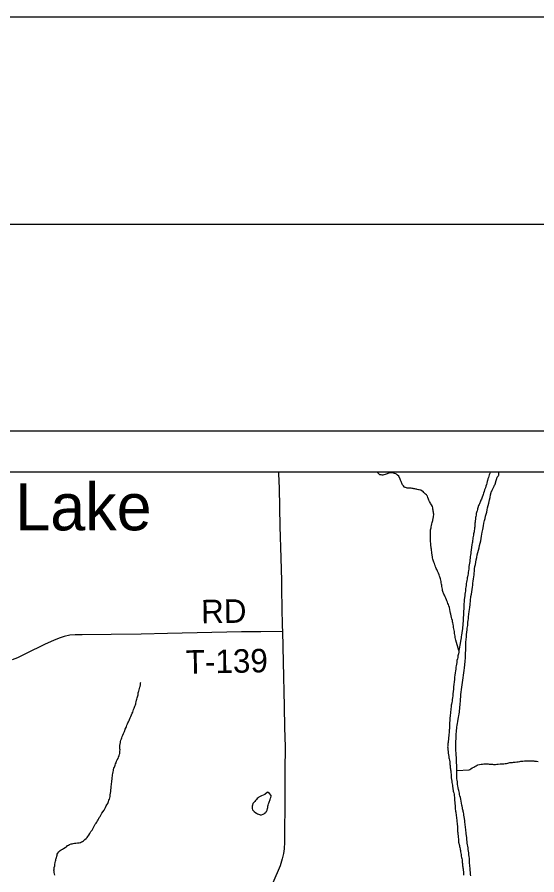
# Model space of a CAD drawing. Extents: x 10.6 to 44.6, y -2.6 to 23.4.
# Drawn here: x 16.174 to 17.431, y 21.353 to 23.426 of the extents above; entities that cross this region are included whole.
import ezdxf

# ---------------------------------------------------------------- set-up
doc = ezdxf.new("R2010")
doc.units = 0
for name, color, linetype in [('GM_X_County', 7, 'Continuous'), ('GM_X_County_Road', 7, 'Continuous'), ('GM_X_Major_River', 7, 'Continuous'), ('GM_X_Minor_Lake', 7, 'Continuous'), ('GM_X_Minor_Lake_Text', 7, 'Continuous'), ('GM_X_Minor_River', 7, 'Continuous'), ('GM_X_Township', 7, 'Continuous'), ('GM_X_Township_Road', 7, 'Continuous'), ('GM_X_Township_Road_Text', 7, 'Continuous'), ('SH_Border', 7, 'Continuous'), ('SH_Cut_Line', 7, 'Continuous'), ('SH_Data', 7, 'Continuous')]:
    doc.layers.add(name, color=color, linetype=linetype)

msp = doc.modelspace()

# ---------------------------------------------------------------- linework, layer by layer
at = {"layer": 'GM_X_County'}
msp.add_lwpolyline([(20.0033, 15.5302), (20.0033, 22.3267), (13.2033, 22.3267), (13.2033, 15.5267), (19.8413, 15.5267)], dxfattribs=at)
at = {"layer": 'GM_X_County_Road'}
msp.add_lwpolyline([(16.8061, 22.3267), (16.8061, 22.3229), (16.8073, 22.2883), (16.8094, 22.1953), (16.8119, 22.1196), (16.8129, 22.0638), (16.8133, 22.0423), (16.8148, 21.9554), (16.8155, 21.9415), (16.817, 21.868), (16.8194, 21.7601), (16.8208, 21.7092), (16.8218, 21.6629), (16.8216, 21.6055), (16.8211, 21.5206), (16.8206, 21.4588), (16.8206, 21.4326), (16.8194, 21.4166), (16.8177, 21.4047), (16.8148, 21.3924), (16.8097, 21.3754), (16.7927, 21.3342)], dxfattribs=at)
at = {"layer": 'GM_X_Major_River'}
for points in [[(17.3176, 22.3267), (17.3169, 22.3237), (17.3158, 22.3203), (17.3147, 22.3169), (17.3137, 22.3134), (17.3126, 22.3104), (17.3115, 22.3069), (17.3108, 22.3039), (17.3098, 22.3004), (17.3087, 22.2966), (17.3073, 22.2928), (17.3062, 22.2886), (17.3044, 22.2836), (17.3034, 22.2798), (17.3019, 22.2759), (17.3009, 22.2725), (17.2976, 22.2641), (17.2969, 22.2614), (17.2954, 22.2591), (17.2947, 22.2568), (17.2936, 22.2545), (17.2925, 22.2525), (17.2918, 22.2503), (17.2911, 22.2483), (17.29, 22.246), (17.2882, 22.2403), (17.2875, 22.238), (17.2872, 22.2361), (17.2861, 22.2334), (17.2858, 22.2315)], [(17.3207, 22.2805), (17.3219, 22.2804), (17.3219, 22.281), (17.3226, 22.2829), (17.3245, 22.2861), (17.3258, 22.29), (17.3277, 22.2925), (17.3283, 22.2951), (17.3296, 22.297), (17.3303, 22.2983), (17.3309, 22.2989), (17.3309, 22.2996), (17.3309, 22.3008), (17.3347, 22.3143), (17.3373, 22.3168), (17.3379, 22.3187), (17.3386, 22.3194), (17.3386, 22.3213), (17.3392, 22.3251), (17.3396, 22.3267)], [(17.2762, 22.0584), (17.2768, 22.0634), (17.2778, 22.0691), (17.2785, 22.074), (17.2788, 22.0786), (17.2791, 22.0828), (17.2797, 22.0874), (17.28, 22.0927), (17.281, 22.0984), (17.282, 22.1038), (17.2831, 22.1091), (17.2841, 22.1148), (17.2855, 22.1205), (17.2865, 22.127), (17.2883, 22.1328), (17.2897, 22.1381), (17.2911, 22.1435), (17.2921, 22.1496), (17.2935, 22.1553), (17.2949, 22.161), (17.2959, 22.1667), (17.2969, 22.1721), (17.298, 22.1771), (17.2986, 22.182), (17.3, 22.1881), (17.3017, 22.1969), (17.3027, 22.2034), (17.3045, 22.2095), (17.3059, 22.2148), (17.3069, 22.2202), (17.308, 22.2255), (17.3094, 22.2301), (17.3104, 22.2355), (17.3118, 22.2404), (17.3132, 22.2462), (17.3146, 22.2519), (17.316, 22.2595), (17.3177, 22.2656), (17.3188, 22.2717), (17.3202, 22.2775), (17.3207, 22.2805)], [(17.2858, 22.2315), (17.285, 22.2292), (17.2843, 22.2265), (17.284, 22.2246), (17.2837, 22.2227), (17.283, 22.2197), (17.2826, 22.2174), (17.2823, 22.2147), (17.282, 22.2117), (17.2817, 22.2098), (17.2813, 22.2078), (17.2814, 22.2059), (17.281, 22.2037), (17.2811, 22.2018), (17.2807, 22.1999), (17.2808, 22.1976), (17.2805, 22.1949), (17.2801, 22.1922), (17.2798, 22.1892), (17.2795, 22.1858), (17.2788, 22.1823), (17.2778, 22.1778), (17.2775, 22.1747), (17.2768, 22.1713), (17.2761, 22.1678), (17.2758, 22.1648), (17.2755, 22.1617), (17.2751, 22.1598), (17.2748, 22.1576), (17.2741, 22.1553), (17.2738, 22.1515), (17.2718, 22.1381), (17.2711, 22.1339), (17.2708, 22.1297), (17.2701, 22.1259), (17.2698, 22.1225), (17.2695, 22.1187), (17.2689, 22.1149), (17.2686, 22.1107), (17.2679, 22.1065), (17.2672, 22.1027), (17.2665, 22.0985), (17.2659, 22.0928), (17.2652, 22.0886), (17.2646, 22.0848), (17.2643, 22.081), (17.2636, 22.0775), (17.2633, 22.0741), (17.2626, 22.0714), (17.2622, 22.0684), (17.2616, 22.0649), (17.2609, 22.0611), (17.2602, 22.0573), (17.2595, 22.0531), (17.2589, 22.0485), (17.2585, 22.0455), (17.2582, 22.0424), (17.2579, 22.0394), (17.2572, 22.0356), (17.2569, 22.0318), (17.2567, 22.0276), (17.256, 22.0234), (17.2553, 22.0184), (17.2551, 22.0135), (17.2544, 22.0085), (17.2541, 22.0028), (17.2538, 21.999), (17.2539, 21.9956), (17.2536, 21.9918), (17.2533, 21.988), (17.2534, 21.9842), (17.2531, 21.98), (17.2528, 21.9762), (17.2529, 21.9728), (17.2526, 21.969), (17.2523, 21.9656), (17.252, 21.9614), (17.2517, 21.9561), (17.251, 21.9519), (17.2507, 21.9481), (17.2501, 21.9439), (17.2488, 21.9328), (17.2481, 21.9294), (17.2478, 21.926), (17.2471, 21.9221), (17.2464, 21.918), (17.2454, 21.9126), (17.2448, 21.9084), (17.2437, 21.9038), (17.243, 21.8996), (17.2424, 21.8954), (17.2417, 21.8916), (17.241, 21.8878), (17.2403, 21.8851), (17.2396, 21.8825), (17.2393, 21.879), (17.2386, 21.8756), (17.2375, 21.8718), (17.2369, 21.8665), (17.2362, 21.8623), (17.2359, 21.8585)], [(17.242, 21.5569), (17.2412, 21.5599), (17.2403, 21.5641), (17.2395, 21.5683), (17.239, 21.5717), (17.2386, 21.5751), (17.2385, 21.5785), (17.2381, 21.5819), (17.2376, 21.5857), (17.2375, 21.5891), (17.2374, 21.5933), (17.2373, 21.5975), (17.2369, 21.6016), (17.2372, 21.6058), (17.237, 21.6111), (17.237, 21.6153), (17.2369, 21.6195), (17.2368, 21.6237), (17.2367, 21.6275), (17.2366, 21.6313), (17.2362, 21.6347), (17.2361, 21.6381), (17.2356, 21.6419), (17.2356, 21.6453), (17.2355, 21.6487), (17.235, 21.6529), (17.2349, 21.6567), (17.2349, 21.6601), (17.2348, 21.6639), (17.2347, 21.6685), (17.235, 21.6734), (17.2352, 21.6776), (17.2355, 21.6814), (17.2355, 21.6848), (17.2358, 21.6879), (17.2357, 21.6913), (17.236, 21.6943), (17.2363, 21.6989), (17.2366, 21.7027), (17.2373, 21.7069), (17.2376, 21.7107), (17.2382, 21.7149), (17.2389, 21.7191), (17.2396, 21.7237), (17.2416, 21.7343), (17.2419, 21.7378), (17.2426, 21.7427), (17.2433, 21.7465), (17.2436, 21.7503), (17.2442, 21.7545), (17.2445, 21.7591), (17.2452, 21.7633), (17.2455, 21.7679), (17.2458, 21.7724), (17.246, 21.7777), (17.2467, 21.7835), (17.2469, 21.7892), (17.2476, 21.7949), (17.2486, 21.8017), (17.2496, 21.8071), (17.2502, 21.8124), (17.2513, 21.8181), (17.2519, 21.8242), (17.2525, 21.8299), (17.2532, 21.8357), (17.2538, 21.8414), (17.2548, 21.8475), (17.2554, 21.8539), (17.2564, 21.8608), (17.2574, 21.8699), (17.2583, 21.8776), (17.2586, 21.8844), (17.2585, 21.8901), (17.2587, 21.8958), (17.259, 21.9023), (17.2592, 21.9091), (17.2594, 21.9156), (17.2601, 21.922), (17.2607, 21.9285), (17.2609, 21.9342), (17.2616, 21.9396), (17.2622, 21.9453), (17.2625, 21.9495), (17.2628, 21.9529), (17.2635, 21.9563), (17.2638, 21.9601), (17.2641, 21.9643), (17.2648, 21.9685), (17.2651, 21.9727), (17.2653, 21.9773), (17.266, 21.9833), (17.2673, 21.9902), (17.2683, 21.9997), (17.2696, 22.007), (17.2715, 22.026), (17.2725, 22.0317), (17.2732, 22.0378), (17.2742, 22.0432), (17.2748, 22.0485), (17.2759, 22.0539), (17.2762, 22.0584)], [(17.2359, 21.8585), (17.2352, 21.855), (17.2346, 21.8508), (17.2339, 21.8463), (17.2333, 21.8413), (17.2326, 21.836), (17.232, 21.831), (17.2313, 21.8257), (17.2307, 21.82), (17.2301, 21.8131), (17.2294, 21.8078), (17.2288, 21.8024), (17.2281, 21.7967), (17.2275, 21.791), (17.2272, 21.7857), (17.2266, 21.7811), (17.2259, 21.7769), (17.2256, 21.7731), (17.2249, 21.7697), (17.2246, 21.7663), (17.2239, 21.7632), (17.2236, 21.759), (17.2229, 21.7556), (17.2226, 21.7518), (17.2223, 21.7484), (17.222, 21.7457), (17.2217, 21.743), (17.2214, 21.74), (17.221, 21.7369), (17.2207, 21.7331), (17.2204, 21.7297), (17.2199, 21.7179), (17.2196, 21.7149), (17.2197, 21.7118), (17.2193, 21.7092), (17.2194, 21.7065), (17.2191, 21.7038), (17.2188, 21.7004), (17.2185, 21.697), (17.2182, 21.6932), (17.2179, 21.6894), (17.2172, 21.6856), (17.2169, 21.6806), (17.2162, 21.6764), (17.2159, 21.6734), (17.2156, 21.6707), (17.2153, 21.6673), (17.2153, 21.6654), (17.215, 21.6631), (17.2151, 21.6604), (17.2151, 21.657), (17.2156, 21.6547), (17.216, 21.6529), (17.216, 21.6506), (17.2165, 21.6487), (17.2165, 21.6468), (17.2169, 21.6449), (17.2173, 21.643), (17.2178, 21.6411), (17.2178, 21.6392), (17.2182, 21.6366), (17.2187, 21.6339), (17.2195, 21.6305), (17.22, 21.6263), (17.2204, 21.6229), (17.2205, 21.6203), (17.2209, 21.6176), (17.2214, 21.615), (17.2214, 21.6123), (17.2219, 21.61), (17.2219, 21.607), (17.2224, 21.6047), (17.2228, 21.6025), (17.2228, 21.5998), (17.2233, 21.5964), (17.2233, 21.5941), (17.2238, 21.5919), (17.2238, 21.5896), (17.2239, 21.5877), (17.2248, 21.5801), (17.2252, 21.5767), (17.2261, 21.5733), (17.2265, 21.5699), (17.227, 21.5668), (17.2274, 21.5631), (17.2279, 21.5608), (17.2283, 21.5585), (17.2287, 21.5559), (17.2295, 21.5536), (17.23, 21.5513), (17.2304, 21.5483), (17.2309, 21.5449), (17.2313, 21.5407), (17.2318, 21.5369), (17.2319, 21.5335), (17.2324, 21.5286), (17.2324, 21.5248), (17.2329, 21.5214), (17.233, 21.518), (17.233, 21.5149), (17.2335, 21.5123)], [(17.2708, 21.3508), (17.2707, 21.3543), (17.2703, 21.3573), (17.2702, 21.3603), (17.2698, 21.3626), (17.2697, 21.3653), (17.2693, 21.3679), (17.2692, 21.3702), (17.2688, 21.3736), (17.2687, 21.3774), (17.2682, 21.3812), (17.2681, 21.385), (17.2681, 21.3888), (17.2676, 21.393), (17.2671, 21.3979), (17.2666, 21.4021), (17.2662, 21.4062), (17.2657, 21.4104), (17.2648, 21.4146), (17.2644, 21.4183), (17.2639, 21.4225), (17.2631, 21.4263), (17.2626, 21.4301), (17.2621, 21.4342), (17.2617, 21.4384), (17.2612, 21.443), (17.2607, 21.4483), (17.2602, 21.4524), (17.2598, 21.4562), (17.2593, 21.4596), (17.2589, 21.4634), (17.2584, 21.4672), (17.2579, 21.4703), (17.2575, 21.4733), (17.2571, 21.4763), (17.2566, 21.4797), (17.2565, 21.4839), (17.2556, 21.4896), (17.2552, 21.4937), (17.2543, 21.4975), (17.2539, 21.5009), (17.253, 21.5043), (17.2526, 21.5066), (17.2522, 21.5085), (17.2518, 21.5108), (17.2513, 21.513), (17.2509, 21.5157), (17.2501, 21.5191), (17.2496, 21.5221), (17.2488, 21.5267), (17.2466, 21.5365), (17.2458, 21.5407), (17.2446, 21.5441), (17.2441, 21.5478), (17.2433, 21.5509), (17.2425, 21.5539), (17.242, 21.5569)], [(17.2335, 21.5123), (17.2339, 21.5092), (17.2343, 21.507), (17.2348, 21.5047), (17.2352, 21.5021), (17.2353, 21.499), (17.2357, 21.4964), (17.2362, 21.4926), (17.2366, 21.4899), (17.2371, 21.4861), (17.2371, 21.4839), (17.2376, 21.4812), (17.238, 21.4782), (17.2384, 21.4748), (17.2385, 21.4714), (17.239, 21.4672), (17.2391, 21.463), (17.2392, 21.4584), (17.2396, 21.4558), (17.2397, 21.4535), (17.2397, 21.4512), (17.2401, 21.449), (17.2402, 21.4463), (17.2406, 21.4433), (17.2411, 21.4403), (17.2412, 21.4372), (17.2412, 21.4346), (17.2416, 21.4323), (17.2433, 21.4243), (17.2438, 21.4221), (17.2442, 21.4198), (17.245, 21.4164), (17.2454, 21.4145), (17.2459, 21.4119), (17.2463, 21.4088), (17.2468, 21.4058), (17.2476, 21.4028), (17.2481, 21.3986), (17.2489, 21.3956), (17.2493, 21.3926), (17.2498, 21.3895), (17.2502, 21.3865), (17.2503, 21.3835), (17.2507, 21.3808), (17.2512, 21.3782), (17.2512, 21.3755), (17.2517, 21.3729), (17.2521, 21.3702), (17.2522, 21.3679), (17.2526, 21.3645), (17.2531, 21.3607), (17.2531, 21.3584), (17.2532, 21.3565), (17.2532, 21.3546), (17.2532, 21.3524)]]:
    msp.add_lwpolyline(points, dxfattribs=at)
at = {"layer": 'GM_X_Minor_Lake'}
for points in [[(16.7795, 21.5529), (16.7728, 21.5479), (16.769, 21.5459), (16.7649, 21.5443), (16.7619, 21.5427), (16.7588, 21.5415), (16.757, 21.5399), (16.7547, 21.538), (16.7525, 21.5356), (16.7503, 21.5329), (16.7484, 21.531), (16.7466, 21.5283), (16.7443, 21.5256), (16.7429, 21.5221), (16.7426, 21.5195), (16.7422, 21.5176), (16.7423, 21.5157), (16.7423, 21.5138), (16.7431, 21.5107), (16.7455, 21.5078), (16.7474, 21.5063), (16.7509, 21.5033), (16.7532, 21.5022), (16.7552, 21.5007), (16.7575, 21.4997), (16.7598, 21.4989)], [(16.7795, 21.5529), (16.7728, 21.5479), (16.769, 21.5459), (16.7649, 21.5443), (16.7619, 21.5427), (16.7588, 21.5415), (16.757, 21.5399), (16.7547, 21.538), (16.7525, 21.5356), (16.7503, 21.5329), (16.7484, 21.531), (16.7466, 21.5283), (16.7443, 21.5256), (16.7429, 21.5221), (16.7426, 21.5195), (16.7422, 21.5176), (16.7423, 21.5157), (16.7423, 21.5138), (16.7431, 21.5107), (16.7455, 21.5078), (16.7474, 21.5063), (16.7509, 21.5033), (16.7532, 21.5022), (16.7552, 21.5007), (16.7575, 21.4997), (16.7598, 21.4989), (16.762, 21.4986), (16.7647, 21.4987), (16.7689, 21.4999), (16.7707, 21.5011), (16.7734, 21.5027), (16.7749, 21.5046), (16.7771, 21.5069), (16.7789, 21.51), (16.7796, 21.5134), (16.7799, 21.5161), (16.7806, 21.5195), (16.7813, 21.5222), (16.782, 21.5249), (16.7824, 21.5268), (16.7831, 21.5291), (16.7842, 21.5314), (16.7849, 21.5333), (16.7856, 21.5356), (16.7867, 21.5387), (16.7874, 21.5406), (16.7881, 21.5433), (16.7881, 21.5455), (16.7841, 21.5504), (16.7811, 21.5522), (16.7799, 21.5526), (16.7795, 21.5529)], [(16.7598, 21.4989), (16.762, 21.4986), (16.7647, 21.4987), (16.7689, 21.4999), (16.7707, 21.5011), (16.7734, 21.5027), (16.7749, 21.5046), (16.7771, 21.5069), (16.7789, 21.51), (16.7796, 21.5134), (16.7799, 21.5161), (16.7806, 21.5195), (16.7813, 21.5222), (16.782, 21.5249), (16.7824, 21.5268), (16.7831, 21.5291), (16.7842, 21.5314), (16.7849, 21.5333), (16.7856, 21.5356), (16.7867, 21.5387), (16.7874, 21.5406), (16.7881, 21.5433), (16.7881, 21.5455), (16.7841, 21.5504), (16.7811, 21.5522), (16.7799, 21.5526), (16.7795, 21.5529)]]:
    msp.add_lwpolyline(points, dxfattribs=at)
at = {"layer": 'GM_X_Minor_River'}
for points in [[(17.181, 22.2205), (17.1813, 22.2232), (17.1813, 22.2254), (17.1812, 22.2273), (17.1808, 22.2296), (17.1804, 22.2326), (17.1799, 22.2345), (17.1795, 22.2372), (17.179, 22.2406), (17.1782, 22.244), (17.1762, 22.2474), (17.1747, 22.25), (17.1739, 22.2519), (17.1711, 22.256), (17.1699, 22.2586), (17.1687, 22.2616), (17.1675, 22.2654), (17.1663, 22.2684), (17.1651, 22.2703), (17.1635, 22.2722), (17.1616, 22.2736), (17.1597, 22.2751), (17.1573, 22.2774), (17.1558, 22.2796), (17.1535, 22.2811), (17.15, 22.2833), (17.1465, 22.284), (17.1446, 22.2843), (17.1416, 22.285), (17.1397, 22.2853), (17.1378, 22.2857), (17.1355, 22.286), (17.1336, 22.2867), (17.1313, 22.287), (17.129, 22.2874), (17.1267, 22.2877), (17.1244, 22.288), (17.1225, 22.288), (17.1206, 22.288), (17.1175, 22.2883), (17.1153, 22.2886), (17.113, 22.2893), (17.111, 22.2896), (17.1099, 22.2915), (17.1083, 22.2938), (17.1056, 22.2964), (17.104, 22.2998), (17.1036, 22.302), (17.1024, 22.3039), (17.1016, 22.3058), (17.1008, 22.3077), (17.1, 22.3099), (17.0968, 22.3171), (17.094, 22.3197), (17.0913, 22.3215), (17.0894, 22.3226), (17.0867, 22.3233), (17.0837, 22.3244), (17.0818, 22.3247), (17.0783, 22.3254), (17.0738, 22.3242), (17.0704, 22.3237), (17.0685, 22.3229), (17.0666, 22.3221), (17.0643, 22.3213), (17.0609, 22.3201), (17.0583, 22.3197), (17.0564, 22.3192), (17.0541, 22.3199), (17.0514, 22.3203), (17.0468, 22.3244), (17.0452, 22.3262), (17.0449, 22.3267)], [(17.2424, 21.8954), (17.2346, 21.9204), (17.2341, 21.9238), (17.2333, 21.9272), (17.2329, 21.9302), (17.2324, 21.9336), (17.232, 21.937), (17.2315, 21.9412), (17.2307, 21.945), (17.2302, 21.948), (17.2294, 21.951), (17.2289, 21.9548), (17.2281, 21.9593), (17.2272, 21.9624), (17.2268, 21.965), (17.2264, 21.968), (17.2255, 21.9718), (17.2247, 21.9752), (17.223, 21.9832), (17.2222, 21.9862), (17.2213, 21.9896), (17.2205, 21.9945), (17.2192, 21.9994), (17.218, 22.0036), (17.2168, 22.007), (17.2156, 22.0092), (17.2148, 22.0123), (17.2132, 22.0156), (17.2123, 22.0183), (17.2107, 22.022), (17.2092, 22.025), (17.2075, 22.0292), (17.206, 22.0322), (17.2048, 22.0341), (17.204, 22.036), (17.2035, 22.0382), (17.2027, 22.0409), (17.2023, 22.0439), (17.2014, 22.0473), (17.201, 22.0507), (17.2006, 22.0534), (17.2001, 22.056), (17.1997, 22.059), (17.1992, 22.0624), (17.1988, 22.0659), (17.1979, 22.0689), (17.1971, 22.0711), (17.1959, 22.0734), (17.1955, 22.0757), (17.1943, 22.0787), (17.1927, 22.0828), (17.1907, 22.0873), (17.1891, 22.0911), (17.1875, 22.0941), (17.1867, 22.096), (17.1855, 22.0982), (17.1847, 22.1009), (17.1839, 22.1031), (17.1831, 22.1062), (17.1819, 22.1088), (17.181, 22.1118), (17.1802, 22.1141), (17.1794, 22.1167), (17.1786, 22.1194), (17.1782, 22.122), (17.1768, 22.1307), (17.1764, 22.1341), (17.1763, 22.1376), (17.1759, 22.1406), (17.175, 22.1432), (17.175, 22.1455), (17.1745, 22.1493), (17.1745, 22.152), (17.174, 22.1554), (17.1736, 22.158), (17.1735, 22.1611), (17.1735, 22.1641), (17.1734, 22.1671), (17.1733, 22.1709), (17.1736, 22.1747), (17.1735, 22.1785), (17.1735, 22.182), (17.1738, 22.1846), (17.1737, 22.1869), (17.174, 22.1899), (17.1748, 22.1922), (17.1751, 22.1949), (17.1758, 22.198), (17.1768, 22.2018), (17.1775, 22.2048), (17.1782, 22.2071), (17.1789, 22.2098), (17.1793, 22.2121), (17.18, 22.214), (17.1803, 22.2159), (17.1807, 22.2178), (17.181, 22.2205)], [(16.4387, 21.7123), (16.4394, 21.715), (16.4408, 21.7181), (16.4419, 21.7208), (16.443, 21.7231), (16.4445, 21.7261), (16.4459, 21.7292), (16.4474, 21.7327), (16.4488, 21.7365), (16.4506, 21.7403), (16.4521, 21.7438), (16.4535, 21.7469), (16.4546, 21.7495), (16.4557, 21.7534), (16.4571, 21.7561), (16.4579, 21.7584), (16.4589, 21.7614), (16.46, 21.7641), (16.4607, 21.7664), (16.4611, 21.7687), (16.4621, 21.7717), (16.4628, 21.7752), (16.4635, 21.7782), (16.4646, 21.7813), (16.4653, 21.784), (16.4656, 21.7863), (16.4663, 21.7886), (16.4667, 21.7905), (16.467, 21.7931), (16.4677, 21.7958), (16.4684, 21.7977), (16.4687, 21.8008), (16.4698, 21.8034), (16.4705, 21.8069), (16.4716, 21.8088), (16.4723, 21.8126), (16.4726, 21.8172), (16.4729, 21.8183)], [(16.2834, 21.4153), (16.2864, 21.4172), (16.2898, 21.4192), (16.2924, 21.4208), (16.2943, 21.4223), (16.2957, 21.4243), (16.298, 21.4251), (16.301, 21.4267), (16.3044, 21.4283), (16.3067, 21.4287), (16.3093, 21.4291), (16.3124, 21.4296), (16.3162, 21.43), (16.3196, 21.4305), (16.3241, 21.431), (16.3271, 21.4318), (16.3298, 21.433), (16.332, 21.4342), (16.3343, 21.4357), (16.3373, 21.4385), (16.3406, 21.4412), (16.3433, 21.4435), (16.3451, 21.4459), (16.3473, 21.4493), (16.3495, 21.4536), (16.3525, 21.4582), (16.3558, 21.4617), (16.3576, 21.4659), (16.3602, 21.4709), (16.3627, 21.4755), (16.3649, 21.4786), (16.3668, 21.4809), (16.3683, 21.4836), (16.3697, 21.4867), (16.3712, 21.4894), (16.3726, 21.4921), (16.3745, 21.4948), (16.3771, 21.499), (16.3789, 21.5021), (16.3841, 21.5098), (16.3859, 21.5129), (16.3877, 21.5163), (16.3896, 21.5198), (16.391, 21.5229), (16.3929, 21.5255), (16.3939, 21.5279), (16.395, 21.5305), (16.3961, 21.5336), (16.3972, 21.5367), (16.3979, 21.5397), (16.3986, 21.5428), (16.3992, 21.547), (16.3999, 21.5512), (16.4006, 21.555), (16.4009, 21.5588), (16.4012, 21.5633), (16.4015, 21.5675), (16.4018, 21.5706), (16.4025, 21.5744), (16.4028, 21.5774), (16.4031, 21.5809), (16.4034, 21.5847), (16.4041, 21.5889), (16.4044, 21.5923), (16.4047, 21.595), (16.4054, 21.5984), (16.406, 21.6022), (16.4067, 21.6056), (16.4074, 21.6083), (16.4081, 21.6114), (16.4092, 21.6137), (16.4099, 21.616), (16.411, 21.6187), (16.4117, 21.6217), (16.4132, 21.6244), (16.4142, 21.6278), (16.4161, 21.6313), (16.4179, 21.6348), (16.419, 21.6378), (16.4204, 21.6417), (16.4215, 21.6451), (16.4222, 21.647), (16.4225, 21.6497), (16.4225, 21.6527), (16.4228, 21.6554), (16.4227, 21.658), (16.4227, 21.6603), (16.4226, 21.663), (16.4226, 21.666), (16.4236, 21.6729), (16.4239, 21.6759), (16.4249, 21.679), (16.426, 21.6821), (16.4271, 21.6847), (16.4278, 21.6878), (16.4292, 21.6912), (16.4311, 21.6951), (16.4333, 21.6997), (16.4354, 21.7054), (16.4376, 21.7097), (16.4387, 21.7123)], [(17.2372, 21.6058), (17.2668, 21.6076), (17.2687, 21.6084), (17.2713, 21.61), (17.2743, 21.6119), (17.2785, 21.6139), (17.2811, 21.6155), (17.2837, 21.6171), (17.2863, 21.6183), (17.2882, 21.6191), (17.2924, 21.6203), (17.2958, 21.6212), (17.2992, 21.6212), (17.3026, 21.6217), (17.3106, 21.6215), (17.3129, 21.6215), (17.3152, 21.6212), (17.3179, 21.6209), (17.3209, 21.6206), (17.3236, 21.6206), (17.3259, 21.6203), (17.3281, 21.6203), (17.3308, 21.6204), (17.3338, 21.6208), (17.3373, 21.6209), (17.3422, 21.6214), (17.3464, 21.6219), (17.3506, 21.622), (17.3544, 21.6224), (17.3574, 21.6229), (17.3604, 21.6233), (17.3631, 21.6241), (17.3657, 21.6246), (17.368, 21.6246), (17.3699, 21.625), (17.3718, 21.6251), (17.3744, 21.6255), (17.3786, 21.626), (17.382, 21.6264), (17.3858, 21.6269), (17.3892, 21.6274), (17.3923, 21.6278), (17.3965, 21.6283), (17.4006, 21.6287), (17.4044, 21.6292), (17.4078, 21.6293), (17.4109, 21.629), (17.4139, 21.629), (17.4181, 21.6291), (17.4208, 21.6288), (17.4231, 21.6289), (17.4254, 21.6285), (17.4276, 21.6282), (17.4303, 21.6279), (17.4341, 21.6276)], [(16.2649, 21.3529), (16.2641, 21.3559), (16.2637, 21.359), (16.2632, 21.362), (16.2631, 21.365), (16.2635, 21.3673), (16.2638, 21.3711), (16.2648, 21.375), (16.2651, 21.3788), (16.2658, 21.383), (16.2669, 21.3864), (16.2672, 21.3891), (16.2679, 21.391), (16.2682, 21.3933), (16.2704, 21.4009), (16.2711, 21.4036), (16.2725, 21.4059), (16.2748, 21.4094), (16.2777, 21.4121), (16.2804, 21.4137), (16.2834, 21.4153)]]:
    msp.add_lwpolyline(points, dxfattribs=at)
at = {"layer": 'GM_X_Township'}
msp.add_line((19.9701, 22.3267), (15.2363, 22.3267), dxfattribs=at)
at = {"layer": 'GM_X_Township_Road'}
msp.add_lwpolyline([(16.8155, 21.9415), (16.7636, 21.9407), (16.7166, 21.9405), (16.5374, 21.9369), (16.4737, 21.9352), (16.4017, 21.934), (16.3309, 21.9335), (16.3144, 21.9335), (16.3013, 21.9325), (16.2877, 21.9298), (16.2754, 21.9257), (16.2616, 21.9201), (16.2491, 21.9145), (16.24, 21.9102), (16.2336, 21.9068), (16.2019, 21.8913), (16.175, 21.8782), (16.1622, 21.8733)], dxfattribs=at)
at = {"layer": 'SH_Border'}
msp.add_lwpolyline([(12.6028, 22.9265), (44.1028, 22.9265), (44.1028, 1.9265), (12.6028, 1.9265)], close=True, dxfattribs=at)
at = {"layer": 'SH_Cut_Line'}
msp.add_lwpolyline([(10.6028, 1.4265), (44.6028, 1.4265), (44.6028, 23.4265), (10.6028, 23.4265)], close=True, dxfattribs=at)
at = {"layer": 'SH_Data'}
msp.add_line((13.1028, 22.4265), (20.1028, 22.4265), dxfattribs=at)

# ---------------------------------------------------------------- texts
at = {"layer": 'GM_X_Minor_Lake_Text'}
msp.add_text('Lake', height=0.1137, rotation=0.0635, dxfattribs=at).set_placement((16.1696, 22.1859))
at = {"layer": 'GM_X_Township_Road_Text'}
for s, rotation, p in [('RD', 0.9891, (16.6193, 21.9611)), ('T-139', 1.1237, (16.5823, 21.8393))]:
    msp.add_text(s, height=0.05682, rotation=rotation, dxfattribs=at).set_placement(p)

doc.saveas('drawing.dxf')
